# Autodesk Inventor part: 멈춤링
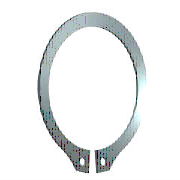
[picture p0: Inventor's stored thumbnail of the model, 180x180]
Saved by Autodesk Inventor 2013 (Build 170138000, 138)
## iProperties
IsCustomPart: 1
Created: 2012-02
Part Number: 멈춤링
Material: 강철, 연강
Description: 리테이닝 링(C형)
Document SubType Name: Modeling
Standard: KS B 1336
Designer: mduedu
Standards Organization: KS
Language: ko-KR
Size Designation: 20 x 1.2
Categories: <MemberInstance><Categories><Category DisplayName="샤프트 부품" InternalName="7f7aeb1f-a693-4053-b835-cee3144e0d98" Mnemonic="SHFT"><Category DisplayName="써클립" Inter
Density: 7.86 g/cm^3
Mass: 1.66547 g
Surface Area: 5.4075 cm^2
Volume: 0.211892 cm^3
Author: mduedu
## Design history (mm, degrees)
sketch "스케치1"
  geometry: L1 (-6, 0)-(6, 0) reference; L2 (0, 20.189)-(0, -80.536) reference; L3 (-48.09, 0)-(48.09, 0) reference; L4 (-0.5, -19.487)-(-0.5, -23.387); L5 (-0.5, -6.54)-(-0.5, -13.29); L6 (-2.795, 2.7)-(3.672, 2.7); L7 (0.5, -6.54)-(0.5, -13.29); L8 (0.5, -19.487)-(0.5, -23.387); C1 r 1 at (-2, -21.219); C2 r 1 at (2, -21.219); A1 r 9.5 centre (0, -10) between (0.5, -19.487) and (-0.5, -19.487); A2 r 12.025 centre (0, -9.325) between (5.071, -20.228) and (-5.071, -20.228); A3 r 13.396 centre (0, -10) between (-2.351, -23.188) and (-0.5, -23.387); A4 r 2 centre (-2, -21.219) between (-3.957, -21.631) and (-2.351, -23.188); A5 r 2 centre (-5.915, -22.042) between (-3.957, -21.631) and (-5.071, -20.228); A6 r 2 centre (5.915, -22.042) between (5.071, -20.228) and (3.957, -21.631); A7 r 2 centre (2, -21.219) between (2.351, -23.188) and (3.957, -21.631); A8 r 13.396 centre (0, -10) between (0.5, -23.387) and (2.351, -23.188)
  constraints: 16 point on circle, 12 end point, 10 centre point, 9 symmetric about line, 5 point on line, 4 tangent, 3 coincident, 2 horizontal, 1 perpendicular, 1 vertical, 5 other
  dimensions: "d0" = 19 diameter of A1 (= ND); "d1" = 3.9 distance of L4.end L4.start (= SRB2); "d6" = 0.5 distance between parallel lines of L2 L5 (= 0.25 x SD5); "d7" = 2.7 distance between parallel lines of L6 L3 (= SRB1); "d8" = 0.675 distance of A1.centre A2.centre (= 0.25 x SRB1); "d9" = 2 radius of A4 (= SD5); "d10" = 2 radius of A5 (= SD5); "d11" = 1.5 distance from line of L4 A4.centre (= 0.75 x SD5); "d12" = 2 diameter of C1 (= SD5); "d13" = 2 diameter of C2 (= SD5); "d14" = 10 distance from line of A1.centre L1 (= 0.5 x WD)
extrude "본체" new body sketch "스케치1" distance "d2" = 1.2 (= SD); taper "d3" = 0 deg
workaxis "Work Axis1"
workplane "Work Plane1"
body "Solid1"
other parameters: "SD" = 1.2 [user parameter; used in 1 equation term], "SRB1" = 2.7 [user parameter; used in 2 equation terms], "ND" = 19 [user parameter; used in 1 equation term], "SRB2" = 3.9 [user parameter; used in 1 equation term], "SD5" = 2 [user parameter; used in 6 equation terms], "d15" = 0, "d16" = 0, "d17" = 0, "d41" = 0, "d42" = 0, "SD3" = 18.5 [user parameter], "WDMAX" = 21 [user parameter]
